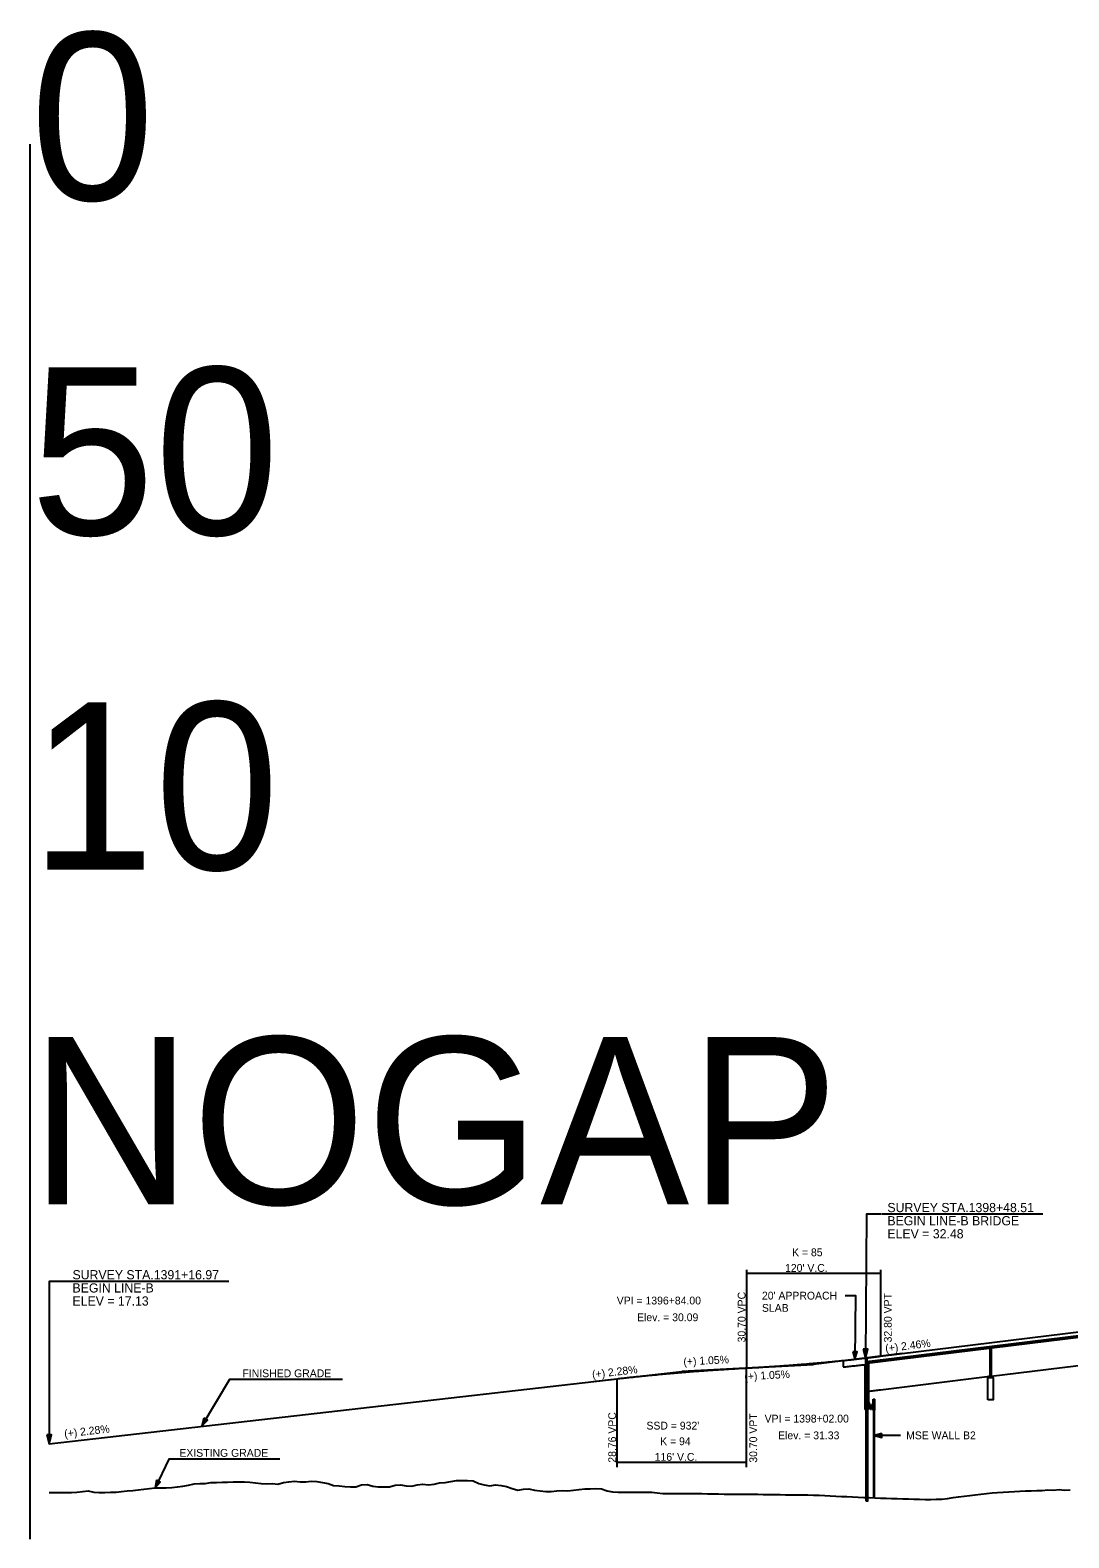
# Model space of a CAD drawing. Extents: x 2360994 to 2383826, y 330623 to 403123.
# Drawn here: x 2368826 to 2369756, y 346874 to 348225 of the extents above; entities that cross this region are included whole.
import ezdxf

# ---------------------------------------------------------------- set-up
doc = ezdxf.new("R2010")
doc.units = 0
for name, color, linetype in [('BR_CENTER LINES', 7, 'Continuous'), ('BR_STRUCTURAL STEEL', 7, 'Continuous'), ('RD_DDB_GradeTX', 7, 'Continuous'), ('RD_DDB_Profile_EX', 7, 'Continuous'), ('RD_DDB_Profile_Lbl', 7, 'Continuous'), ('RD_DDB_Profile_PR', 7, 'Continuous'), ('RD_DDB_StripGrade', 7, 'Continuous'), ('RD_DDB_VCLbl', 7, 'Continuous'), ('RD_GPK_Profile_Cell', 7, 'Continuous'), ('RD_PD_MedBWall', 7, 'Continuous'), ('RD_TX_Profile', 7, 'Continuous'), ('RD_XS_Bridge', 7, 'Continuous')]:
    doc.layers.add(name, color=color, linetype=linetype)

msp = doc.modelspace()

# ---------------------------------------------------------------- linework, layer by layer
at = {"layer": 'BR_CENTER LINES'}
msp.add_line((2369575.2, 347035.4), (2369575.2, 346906.3), dxfattribs=at)
at = {"layer": 'BR_STRUCTURAL STEEL'}
for p, q in [((2369574.4, 346989.3), (2369574.4, 346907.1)), ((2369575.9, 346989.3), (2369575.9, 346906.7))]:
    msp.add_line(p, q, dxfattribs=at)
at = {"layer": 'RD_DDB_GradeTX'}
for p, q in [((2369607, 347039.3), (2369527.6, 347029.5)), ((2369330.1, 347014.2), (2369409.6, 347023.3)), ((2369330.1, 347014.2), (2369409.6, 347023.3)), ((2369489.5, 347027.5), (2369409.6, 347023.3)), ((2369447.7, 347025.3), (2369527.6, 347029.5))]:
    msp.add_line(p, q, dxfattribs=at)
at = {"layer": 'RD_DDB_Profile_EX'}
for points in [[(2368842.5, 346914.9), (2368847.5, 346914.9), (2368852.5, 346914.8), (2368857.5, 346914.7), (2368862.5, 346914.7), (2368867.5, 346915.2), (2368872.5, 346915.7), (2368877.5, 346916.2), (2368882.5, 346915.2), (2368887.5, 346914.8), (2368892.5, 346914.9), (2368897.5, 346915.1), (2368902.5, 346915.2), (2368907.5, 346915.6), (2368912.5, 346916.2), (2368917.5, 346916.7), (2368922.5, 346917.3), (2368927.5, 346917.8), (2368932.5, 346918.3), (2368937.5, 346918.9), (2368942.5, 346919), (2368947.5, 346919), (2368952.5, 346919.2), (2368957.5, 346919.9), (2368962.5, 346920.5), (2368967.5, 346921.5), (2368972.5, 346922.5), (2368977.5, 346922.9), (2368982.5, 346922.9), (2368987.5, 346923.7), (2368992.5, 346923.8), (2368997.5, 346924), (2369002.5, 346924.1), (2369007.5, 346924.3), (2369012.5, 346924.4), (2369017.5, 346924.5), (2369022.5, 346924), (2369027.5, 346923.5), (2369032.5, 346923), (2369037.5, 346922.6), (2369042.5, 346922.9), (2369047.5, 346922.4), (2369052.5, 346923.7), (2369057.5, 346924.4), (2369062.5, 346925), (2369067.5, 346924.4), (2369072.5, 346924.4), (2369077.5, 346925), (2369082.5, 346924.7), (2369087.5, 346923.7), (2369092.5, 346923), (2369097.5, 346921.2), (2369102.5, 346920.7), (2369107.5, 346920.3), (2369112.5, 346920), (2369117.5, 346919.8), (2369122.5, 346921.6), (2369127.5, 346921.9), (2369132.5, 346920.6), (2369137.5, 346920), (2369142.5, 346919.9), (2369147.5, 346919.8), (2369152.5, 346921.5), (2369157.5, 346921.7), (2369162.5, 346920.7), (2369167.5, 346920.5), (2369172.5, 346921.6), (2369177.5, 346922.4), (2369182.5, 346921.7), (2369187.5, 346922.2), (2369192.5, 346923.5), (2369197.5, 346923.7), (2369202.5, 346924.8), (2369207.5, 346925.5), (2369212.5, 346925.5), (2369217.5, 346925.5), (2369222.5, 346925.2), (2369227.5, 346922.8), (2369232.5, 346921.7), (2369237.5, 346920.7), (2369242.5, 346921.6), (2369247.5, 346921.1), (2369252.5, 346920.1), (2369257.5, 346918.5), (2369262.5, 346916.9), (2369267.5, 346917.8), (2369272.5, 346918), (2369277.5, 346916.8), (2369282.5, 346916.4), (2369287.5, 346915.6), (2369292.5, 346915.7), (2369297.5, 346916.3), (2369302.5, 346916.6), (2369307.5, 346916.4), (2369312.5, 346916.8), (2369317.5, 346917.6), (2369322.5, 346918.2), (2369327.5, 346918.2), (2369332.5, 346918.3), (2369337.5, 346918), (2369342.5, 346916.3)], [(2369342.5, 346916.3), (2369347.5, 346915.3), (2369352.5, 346915.1), (2369357.5, 346915.2), (2369362.5, 346915.1), (2369367.5, 346915.1), (2369372.5, 346915.1), (2369377.5, 346915.1), (2369382.5, 346915), (2369387.5, 346914.4), (2369392.5, 346913.8), (2369397.5, 346913.9), (2369402.5, 346914), (2369407.5, 346914), (2369412.5, 346913.9), (2369417.5, 346913.8), (2369422.5, 346913.9), (2369427.5, 346913.8), (2369432.5, 346913.7), (2369437.5, 346913.6), (2369442.5, 346913.5), (2369447.5, 346913.3), (2369452.5, 346913.3), (2369457.5, 346913.3), (2369462.5, 346913.2), (2369467.5, 346913.3), (2369472.5, 346913.4), (2369477.5, 346913.3), (2369482.5, 346913.1), (2369487.5, 346913), (2369492.5, 346912.9), (2369497.5, 346912.9), (2369502.5, 346912.7), (2369507.5, 346912.7), (2369512.5, 346912.7), (2369517.5, 346912.7), (2369522.5, 346912.6), (2369527.5, 346912.4), (2369532.5, 346912.3), (2369537.5, 346912), (2369542.5, 346911.8), (2369547.5, 346911.6), (2369552.5, 346911.3), (2369557.5, 346911.1), (2369562.5, 346910.8), (2369567.5, 346910.6), (2369572.5, 346910.4), (2369577.5, 346910.2), (2369582.5, 346909.9), (2369587.5, 346909.7), (2369592.5, 346909.6), (2369597.5, 346909.5), (2369602.5, 346909.3), (2369607.5, 346909.2), (2369612.5, 346909), (2369617.5, 346908.8), (2369622.5, 346908.7), (2369627.5, 346908.6), (2369632.5, 346908.6), (2369637.5, 346908.7), (2369642.5, 346908.8), (2369647.5, 346909.4), (2369652.5, 346910.3), (2369657.5, 346911), (2369662.5, 346911.6), (2369667.5, 346912.1), (2369672.5, 346912.7), (2369677.5, 346913.3), (2369682.5, 346913.9), (2369687.5, 346914.5), (2369692.5, 346914.9), (2369697.5, 346915.2), (2369702.5, 346915.5), (2369707.5, 346915.7), (2369712.5, 346915.9), (2369717.5, 346916.2), (2369722.5, 346916.4), (2369727.5, 346916.5), (2369732.5, 346916.7), (2369737.5, 346917.3), (2369742.5, 346917), (2369747.5, 346917.6), (2369752.5, 346916.8), (2369757.5, 346917.3)]]:
    msp.add_lwpolyline(points, dxfattribs=at)
at = {"layer": 'RD_DDB_Profile_PR'}
for p, q in [((2369587.6, 347036.9), (2369805.6, 347063.7)), ((2369587.6, 347036.9), (2369805.6, 347063.7)), ((2368842.5, 346958.5), (2369351.6, 347016.7))]:
    msp.add_line(p, q, dxfattribs=at)
for points in [[(2369467.6, 347026.4), (2369470, 347026.5), (2369472.4, 347026.6), (2369474.8, 347026.8), (2369477.2, 347026.9), (2369479.6, 347027), (2369482, 347027.2), (2369484.4, 347027.3), (2369486.8, 347027.5), (2369489.2, 347027.6), (2369491.6, 347027.8), (2369494, 347027.9), (2369496.4, 347028.1), (2369498.8, 347028.3), (2369501.2, 347028.5), (2369503.6, 347028.6), (2369506, 347028.8), (2369508.4, 347029), (2369510.8, 347029.2), (2369513.2, 347029.4), (2369515.6, 347029.6), (2369518, 347029.7), (2369520.4, 347029.9), (2369522.8, 347030.2), (2369525.2, 347030.4), (2369527.6, 347030.6), (2369530, 347030.8), (2369532.4, 347031), (2369534.8, 347031.2), (2369537.2, 347031.4), (2369539.6, 347031.7), (2369542, 347031.9), (2369544.4, 347032.1), (2369546.8, 347032.4), (2369549.2, 347032.6), (2369551.6, 347032.8), (2369554, 347033.1), (2369556.4, 347033.3), (2369558.8, 347033.6), (2369561.2, 347033.8), (2369563.6, 347034.1), (2369566, 347034.4), (2369568.4, 347034.6), (2369570.8, 347034.9), (2369573.2, 347035.2), (2369575.6, 347035.5), (2369578, 347035.7), (2369580.4, 347036), (2369582.8, 347036.3), (2369585.2, 347036.6), (2369587.6, 347036.9)], [(2369467.6, 347026.4), (2369470, 347026.5), (2369472.4, 347026.6), (2369474.8, 347026.8), (2369477.2, 347026.9), (2369479.6, 347027), (2369482, 347027.2), (2369484.4, 347027.3), (2369486.8, 347027.5), (2369489.2, 347027.6), (2369491.6, 347027.8), (2369494, 347027.9), (2369496.4, 347028.1), (2369498.8, 347028.3), (2369501.2, 347028.5), (2369503.6, 347028.6), (2369506, 347028.8), (2369508.4, 347029), (2369510.8, 347029.2), (2369513.2, 347029.4), (2369515.6, 347029.6), (2369518, 347029.7), (2369520.4, 347029.9), (2369522.8, 347030.2), (2369525.2, 347030.4), (2369527.6, 347030.6), (2369530, 347030.8), (2369532.4, 347031), (2369534.8, 347031.2), (2369537.2, 347031.4), (2369539.6, 347031.7), (2369542, 347031.9), (2369544.4, 347032.1), (2369546.8, 347032.4), (2369549.2, 347032.6), (2369551.6, 347032.8), (2369554, 347033.1), (2369556.4, 347033.3), (2369558.8, 347033.6), (2369561.2, 347033.8), (2369563.6, 347034.1), (2369566, 347034.4), (2369568.4, 347034.6), (2369570.8, 347034.9), (2369573.2, 347035.2), (2369575.6, 347035.5), (2369578, 347035.7), (2369580.4, 347036), (2369582.8, 347036.3), (2369585.2, 347036.6), (2369587.6, 347036.9)], [(2369351.6, 347016.7), (2369353.9, 347017), (2369356.2, 347017.2), (2369358.5, 347017.5), (2369360.8, 347017.7), (2369363.2, 347018), (2369365.5, 347018.2), (2369367.8, 347018.5), (2369370.1, 347018.7), (2369372.4, 347019), (2369374.8, 347019.2), (2369377.1, 347019.4), (2369379.4, 347019.7), (2369381.7, 347019.9), (2369384, 347020.1), (2369386.4, 347020.3), (2369388.7, 347020.6), (2369391, 347020.8), (2369393.3, 347021), (2369395.6, 347021.2), (2369398, 347021.4), (2369400.3, 347021.6), (2369402.6, 347021.8), (2369404.9, 347022), (2369407.2, 347022.2), (2369409.6, 347022.4), (2369411.9, 347022.6), (2369414.2, 347022.8), (2369416.5, 347023), (2369418.8, 347023.2), (2369421.2, 347023.4), (2369423.5, 347023.5), (2369425.8, 347023.7), (2369428.1, 347023.9), (2369430.4, 347024), (2369432.8, 347024.2), (2369435.1, 347024.4), (2369437.4, 347024.5), (2369439.7, 347024.7), (2369442, 347024.8), (2369444.4, 347025), (2369446.7, 347025.1), (2369449, 347025.3), (2369451.3, 347025.4), (2369453.6, 347025.6), (2369456, 347025.7), (2369458.3, 347025.8), (2369460.6, 347026), (2369462.9, 347026.1), (2369465.2, 347026.2), (2369467.6, 347026.4)], [(2369351.6, 347016.7), (2369353.9, 347017), (2369356.2, 347017.2), (2369358.5, 347017.5), (2369360.8, 347017.7), (2369363.2, 347018), (2369365.5, 347018.2), (2369367.8, 347018.5), (2369370.1, 347018.7), (2369372.4, 347019), (2369374.8, 347019.2), (2369377.1, 347019.4), (2369379.4, 347019.7), (2369381.7, 347019.9), (2369384, 347020.1), (2369386.4, 347020.3), (2369388.7, 347020.6), (2369391, 347020.8), (2369393.3, 347021), (2369395.6, 347021.2), (2369398, 347021.4), (2369400.3, 347021.6), (2369402.6, 347021.8), (2369404.9, 347022), (2369407.2, 347022.2), (2369409.6, 347022.4), (2369411.9, 347022.6), (2369414.2, 347022.8), (2369416.5, 347023), (2369418.8, 347023.2), (2369421.2, 347023.4), (2369423.5, 347023.5), (2369425.8, 347023.7), (2369428.1, 347023.9), (2369430.4, 347024), (2369432.8, 347024.2), (2369435.1, 347024.4), (2369437.4, 347024.5), (2369439.7, 347024.7), (2369442, 347024.8), (2369444.4, 347025), (2369446.7, 347025.1), (2369449, 347025.3), (2369451.3, 347025.4), (2369453.6, 347025.6), (2369456, 347025.7), (2369458.3, 347025.8), (2369460.6, 347026), (2369462.9, 347026.1), (2369465.2, 347026.2), (2369467.6, 347026.4)]]:
    msp.add_spline(points, degree=3, dxfattribs=at)
at = {"layer": 'RD_DDB_VCLbl'}
for p, q in [((2369467.6, 347114.4), (2369467.6, 347026.4)), ((2369587.6, 347114.4), (2369587.6, 347036.9)), ((2369467.6, 347111.3), (2369587.6, 347111.3)), ((2369467.6, 346937.5), (2369467.6, 347026.4)), ((2369351.6, 346937.5), (2369351.6, 347016.7)), ((2369351.6, 346941.9), (2369467.6, 346941.9))]:
    msp.add_line(p, q, dxfattribs=at)
at = {"layer": 'RD_GPK_Profile_Cell'}
msp.add_line((2368825.6, 346872.9), (2368825.6, 348122.9), dxfattribs=at)
at = {"layer": 'RD_PD_MedBWall'}
for p, q in [((2369576.9, 346996), (2369578.9, 346991)), ((2369576.9, 346994.3), (2369578.9, 346989.3)), ((2369581.1, 346996), (2369579.1, 346991)), ((2369581.1, 346994.3), (2369579.1, 346989.3)), ((2369581.1, 346988.5), (2369581.1, 346998.5)), ((2369581.1, 346998.5), (2369582.6, 346998.5)), ((2369582.6, 346988.5), (2369582.6, 346998.5)), ((2369578.9, 346991), (2369579.1, 346991)), ((2369578.9, 346989.3), (2369579.1, 346989.3)), ((2369581.1, 346988.5), (2369581.6, 346988.5)), ((2369581.6, 346909.9), (2369581.6, 346991)), ((2369581.6, 346991), (2369582.1, 346991)), ((2369582.1, 346909.9), (2369582.1, 346991)), ((2369582.1, 346988.5), (2369582.6, 346988.5))]:
    msp.add_line(p, q, dxfattribs=at)
at = {"layer": 'RD_TX_Profile'}
for p, q in [((2369732.9, 347164.2), (2369588.7, 347164.2)), ((2369003.5, 347104), (2368858.5, 347104)), ((2369105.4, 347016.1), (2369010.8, 347016.1)), ((2369049.4, 346944.8), (2368954.3, 346944.8))]:
    msp.add_line(p, q, dxfattribs=at)
for points in [[(2369588, 347164.2), (2369575.1, 347164.2), (2369574.1, 347035.3)], [(2368858.5, 347104), (2368842.5, 347104), (2368842.5, 346958.5)], [(2369555.9, 347091.2), (2369565.1, 347091.2), (2369564.6, 347034.2)], [(2369010.8, 347016.1), (2369004.2, 347016.1), (2368979.4, 346974.6)], [(2369605.5, 346966), (2369600.1, 346966), (2369582.1, 346966)], [(2368954.3, 346944.8), (2368949.8, 346944.8), (2368937.5, 346918.9)]]:
    msp.add_lwpolyline(points, dxfattribs=at)
for points in [[(2369562.8, 347040.9), (2369564.6, 347034.2), (2369566.5, 347040.9)], [(2369572, 347043.3), (2369574.1, 347035.3), (2369576.3, 347043.2)], [(2368981.3, 346981.3), (2368979.4, 346974.6), (2368984.5, 346979.5)], [(2368840.4, 346966.5), (2368842.5, 346958.5), (2368844.7, 346966.5)], [(2369588.8, 346967.8), (2369582.1, 346966), (2369588.8, 346964.2)], [(2368938.8, 346925.8), (2368937.5, 346918.9), (2368942.1, 346924.2)]]:
    msp.add_lwpolyline(points, close=True, dxfattribs=at)
at = {"layer": 'RD_XS_Bridge'}
for p, q in [((2369587.6, 347033.6), (2369805.6, 347060.4)), ((2369587.6, 347032.3), (2369805.6, 347059.1)), ((2369554.1, 347033.1), (2369554.1, 347027.3)), ((2369574.1, 347035.3), (2369574.1, 347029.4)), ((2369685.6, 347044.4), (2369685.6, 347018.9)), ((2369686.6, 347044.4), (2369686.6, 347019.1)), ((2369573.4, 347029.4), (2369573.4, 346989.3)), ((2369576.9, 347032.3), (2369576.9, 346989.3)), ((2369686.6, 347019.1), (2369797.6, 347032.7)), ((2369587.6, 347006.9), (2369685.6, 347018.9)), ((2369576.9, 347004.3), (2369573.4, 347004.3)), ((2369576.9, 346989.3), (2369573.4, 346989.3))]:
    msp.add_line(p, q, dxfattribs=at)
for points in [[(2369683.6, 346997.7), (2369683.6, 347017.7), (2369688.6, 347017.7), (2369688.6, 346997.7)], [(2369685.1, 347017.7), (2369684.6, 347017.7), (2369684.6, 347019), (2369685.1, 347019)], [(2369687.1, 347017.7), (2369687.6, 347017.7), (2369687.6, 347019), (2369687.1, 347019)]]:
    msp.add_lwpolyline(points, close=True, dxfattribs=at)
for points in [[(2369576.9, 347032.3), (2369578, 347032.4), (2369580.4, 347032.7), (2369582.8, 347033), (2369585.2, 347033.3), (2369587.6, 347033.6)], [(2369554.1, 347027.3), (2369556.4, 347027.5), (2369558.8, 347027.8), (2369561.2, 347028), (2369563.6, 347028.3), (2369566, 347028.5), (2369568.4, 347028.8), (2369570.8, 347029.1), (2369573.2, 347029.3), (2369574.1, 347029.4)], [(2369576.9, 347031), (2369578, 347031.1), (2369580.4, 347031.4), (2369582.8, 347031.7), (2369585.2, 347032), (2369587.6, 347032.3)], [(2369576.9, 347005.6), (2369578, 347005.7), (2369580.4, 347006), (2369582.8, 347006.3), (2369585.2, 347006.6), (2369587.6, 347006.9)]]:
    msp.add_spline(points, degree=3, dxfattribs=at)

# ---------------------------------------------------------------- texts
at = {"layer": 'RD_DDB_GradeTX'}
for s, rotation, p in [('(+) 2.46%', 7.0106, (2369592.2, 347040.4)), ('(+) 1.05%', 3.0038, (2369411.1, 347028.5)), ('(+) 2.28%', 6.5164, (2369329.5, 347017.1)), ('(+) 1.05%', 3.0038, (2369465.7, 347015.3)), ('(+) 2.28%', 6.5164, (2368856.5, 346964))]:
    msp.add_text(s, height=7, rotation=rotation, dxfattribs=at).set_placement(p)
at = {"layer": 'RD_DDB_Profile_Lbl'}
for s, p in [('VPI = 1396+84.00', (2369351.2, 347083.3)), ('Elev. = 30.09', (2369369.4, 347068.3)), ('VPI = 1398+02.00', (2369483.7, 346977.5)), ('Elev. = 31.33', (2369495.8, 346962.5))]:
    msp.add_text(s, height=7, dxfattribs=at).set_placement(p)
at = {"layer": 'RD_DDB_StripGrade'}
for s, p in [('30.70 VPC', (2369466.6, 347049.3)), ('32.80 VPT', (2369597.6, 347049.3)), ('28.76 VPC', (2369350.6, 346941.5)), ('30.70 VPT', (2369477, 346941.5))]:
    msp.add_text(s, height=7, rotation=90, dxfattribs=at).set_placement(p)
at = {"layer": 'RD_DDB_VCLbl'}
for s, p in [('K = 85', (2369508.3, 347126.5)), ("120' V.C.", (2369502, 347112.5)), ("SSD = 932'", (2369377.8, 346971.2)), ('K = 94', (2369390.1, 346957.2)), ("116' V.C.", (2369385.2, 346943.2))]:
    msp.add_text(s, height=7, dxfattribs=at).set_placement(p)
at = {"layer": 'RD_GPK_Profile_Cell'}
for s, p in [('0', (2368825.6, 348072.9)), ('50', (2368825.6, 347772.9)), ('10', (2368825.6, 347472.9)), ('NOGAP', (2368825.6, 347172.9))]:
    msp.add_text(s, height=150, dxfattribs=at).set_placement(p)
at = {"layer": 'RD_TX_Profile'}
for s, height, p in [('SURVEY STA.1398+48.51', 8.235, (2369593.7, 347166)), ('BEGIN LINE-B BRIDGE', 8.235, (2369593.7, 347154.2)), ('ELEV = 32.48', 8.235, (2369593.7, 347142.5)), ('SURVEY STA.1391+16.97', 8.235, (2368863.5, 347105.8)), ('BEGIN LINE-B', 8.235, (2368863.5, 347094)), ('ELEV = 17.13', 8.235, (2368863.5, 347082.3)), ("20' APPROACH", 7, (2369481.3, 347087.7)), ('SLAB', 7, (2369481.3, 347076.7)), ('FINISHED GRADE', 7, (2369015.8, 347018.1)), ('MSE WALL B2', 7, (2369610.5, 346962.5)), ('EXISTING GRADE', 7, (2368959.3, 346946.8))]:
    msp.add_text(s, height=height, dxfattribs=at).set_placement(p)

doc.saveas('drawing.dxf')
